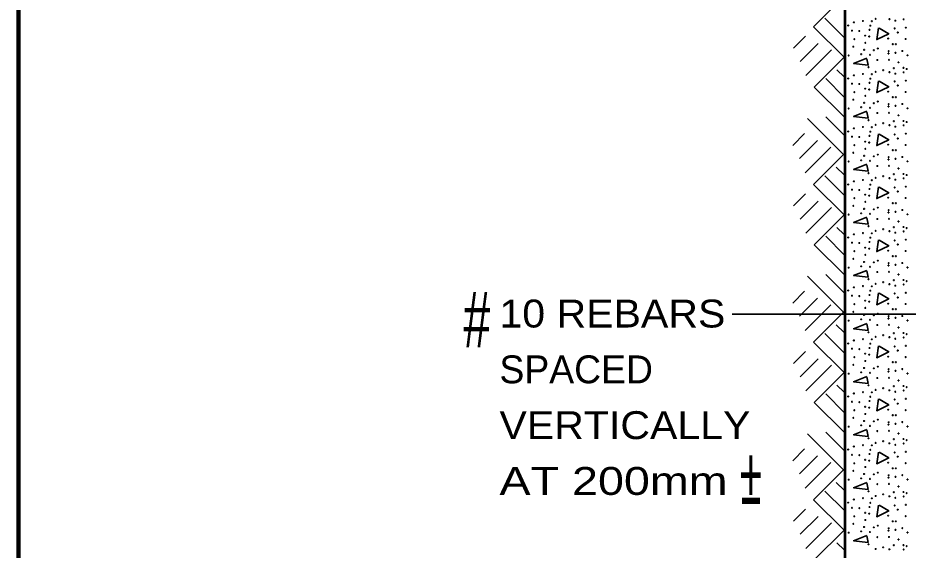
# Model space of a CAD drawing. Extents: x 442 to 1297, y -1132 to -588.
# Drawn here: x 499 to 575.6, y -964.6 to -918.8 of the extents above; entities that cross this region are included whole.
import ezdxf
from ezdxf.enums import TextEntityAlignment as Align

# ---------------------------------------------------------------- set-up
doc = ezdxf.new("R2010")
doc.units = 0
doc.header["$LTSCALE"] = 0.96
doc.layers.add('1', color=7, linetype='Continuous', lineweight=35)

msp = doc.modelspace()

# ---------------------------------------------------------------- linework, layer by layer
at = {"layer": '1', "lineweight": 53}
for q in [(570.1476, -980.7675), (570.1476, -980.5452)]:
    msp.add_line((570.1476, -886.6076), q, dxfattribs=at)
at = {"layer": '1'}
for p, q in [((570.0996, -916.8956), (567.4596, -919.5356)), ((570.0996, -920.4476), (568.4436, -918.7916)), ((570.0996, -922.1516), (567.4596, -919.5356)), ((566.7636, -920.3516), (565.7316, -921.3836)), ((567.8676, -920.9756), (566.3316, -922.5116)), ((569.0196, -921.5276), (566.8116, -923.7356)), ((570.0996, -922.1516), (567.5316, -924.7196)), ((570.0996, -923.8556), (569.4756, -923.2316)), ((570.0996, -925.5836), (568.5156, -923.9996)), ((570.0996, -927.2876), (567.5316, -924.7196)), ((570.0996, -930.5756), (566.9556, -927.4316)), ((570.0996, -928.8716), (568.5156, -927.2876)), ((566.6916, -928.7276), (565.6836, -929.7596)), ((567.7956, -929.3276), (566.2596, -930.8636)), ((568.9476, -929.8796), (566.7396, -932.1116)), ((570.0996, -930.4556), (567.4596, -933.0956)), ((570.0996, -932.2796), (569.4036, -931.6076)), ((570.0996, -934.0076), (568.4436, -932.3516)), ((570.0996, -935.7116), (567.4596, -933.0956)), ((566.7636, -933.9116), (565.7316, -934.9436)), ((567.8676, -934.5356), (566.3316, -936.0716)), ((569.0196, -935.0876), (566.8116, -937.2956)), ((570.0996, -935.7116), (567.5316, -938.2796)), ((570.0996, -937.4156), (569.4756, -936.7916)), ((570.0996, -939.1436), (568.5156, -937.5596)), ((570.0996, -940.8476), (567.5316, -938.2796)), ((570.0996, -942.4316), (568.5156, -940.8476)), ((570.0996, -944.1356), (566.9556, -940.9916)), ((566.6916, -942.2876), (565.6836, -943.3196)), ((567.7956, -942.8876), (566.2596, -944.4236)), ((568.9476, -943.4396), (566.7396, -945.6716)), ((560.4645, -944.2491), (579.7476, -944.2491)), ((570.0996, -944.0156), (567.4596, -946.6556)), ((570.0996, -945.8396), (569.4036, -945.1676)), ((570.0996, -947.5676), (568.4436, -945.9116)), ((570.0996, -949.2716), (567.4596, -946.6556)), ((566.7636, -947.4716), (565.7316, -948.5036)), ((567.8676, -948.0956), (566.3316, -949.6316)), ((569.0196, -948.6476), (566.8116, -950.8556)), ((570.0996, -949.2716), (567.5316, -951.8396)), ((570.0996, -950.9756), (569.4756, -950.3516)), ((570.0996, -952.7036), (568.5156, -951.1196)), ((570.0996, -954.4076), (567.5316, -951.8396)), ((570.0996, -957.6956), (566.9556, -954.5516)), ((570.0996, -955.9916), (568.5156, -954.4076)), ((566.6916, -955.8476), (565.6836, -956.8796)), ((567.7956, -956.4476), (566.2596, -957.9836)), ((568.9476, -956.9996), (566.7396, -959.2316)), ((570.0996, -957.5756), (567.4596, -960.2156)), ((570.0996, -959.3996), (569.4036, -958.7276)), ((570.0996, -961.1276), (568.4436, -959.4716)), ((570.0996, -962.8316), (567.4596, -960.2156)), ((566.7636, -961.0316), (565.7316, -962.0636)), ((567.8676, -961.6556), (566.3316, -963.1916)), ((569.0196, -962.2076), (566.8116, -964.4156)), ((570.0996, -962.8316), (567.5316, -965.3996)), ((570.0996, -964.5356), (569.4756, -963.9116))]:
    msp.add_line(p, q, dxfattribs=at)
at = {"layer": '1', "lineweight": 158}
msp.add_lwpolyline([(1290.7447, -594.0679), (499.0447, -594.1679), (499.1447, -1120.1679)], dxfattribs=at)
at = {"layer": '1'}
for points in [[(573.0974, -919.6547), (573.9374, -920.1347), (572.9054, -920.6387), (573.0494, -919.6307)], [(570.1476, -920.3222), (570.1694, -920.3267), (570.1476, -920.3501)], [(572.0414, -922.2467), (570.9134, -922.7027), (572.1614, -922.8467), (572.0414, -922.2947)], [(573.0974, -924.2147), (573.9374, -924.6947), (572.9054, -925.1987), (573.0494, -924.1907)], [(570.1476, -924.8822), (570.1694, -924.8867), (570.1476, -924.9101)], [(572.0414, -926.8067), (570.9134, -927.2627), (572.1614, -927.4067), (572.0414, -926.8547)], [(570.1476, -929.4422), (570.1694, -929.4467), (570.1476, -929.4701)], [(573.0974, -928.7747), (573.9374, -929.2547), (572.9054, -929.7587), (573.0494, -928.7507)], [(572.0414, -931.3667), (570.9134, -931.8227), (572.1614, -931.9667), (572.0414, -931.4147)], [(570.1476, -934.0022), (570.1694, -934.0067), (570.1476, -934.0301)], [(573.0974, -933.3347), (573.9374, -933.8147), (572.9054, -934.3187), (573.0494, -933.3107)], [(572.0414, -935.9267), (570.9134, -936.3827), (572.1614, -936.5267), (572.0414, -935.9747)], [(573.0974, -937.8947), (573.9374, -938.3747), (572.9054, -938.8787), (573.0494, -937.8707)], [(570.1476, -938.5622), (570.1694, -938.5667), (570.1476, -938.5901)], [(572.0414, -940.4867), (570.9134, -940.9427), (572.1614, -941.0867), (572.0414, -940.5347)], [(573.0974, -942.4547), (573.9374, -942.9347), (572.9054, -943.4387), (573.0494, -942.4307)], [(570.1476, -943.1222), (570.1694, -943.1267), (570.1476, -943.1501)], [(572.0414, -945.0467), (570.9134, -945.5027), (572.1614, -945.6467), (572.0414, -945.0947)], [(573.0974, -947.0147), (573.9374, -947.4947), (572.9054, -947.9987), (573.0494, -946.9907)], [(570.1476, -947.6822), (570.1694, -947.6867), (570.1476, -947.7101)], [(572.0414, -949.6067), (570.9134, -950.0627), (572.1614, -950.2067), (572.0414, -949.6547)], [(573.0974, -951.5747), (573.9374, -952.0547), (572.9054, -952.5587), (573.0494, -951.5507)], [(570.1476, -952.2422), (570.1694, -952.2467), (570.1476, -952.2701)], [(572.0414, -954.1667), (570.9134, -954.6227), (572.1614, -954.7667), (572.0414, -954.2147)], [(573.0974, -956.1347), (573.9374, -956.6147), (572.9054, -957.1187), (573.0494, -956.1107)], [(570.1476, -956.8022), (570.1694, -956.8067), (570.1476, -956.8301)], [(572.0414, -958.7267), (570.9134, -959.1827), (572.1614, -959.3267), (572.0414, -958.7747)], [(573.0974, -960.6947), (573.9374, -961.1747), (572.9054, -961.6787), (573.0494, -960.6707)], [(570.1476, -961.3622), (570.1694, -961.3667), (570.1476, -961.3901)], [(572.0414, -963.2867), (570.9134, -963.7427), (572.1614, -963.8867), (572.0414, -963.3347)]]:
    msp.add_lwpolyline(points, dxfattribs=at)
for centre in [(570.4458, -919.4227), (570.9388, -919.1523), (571.7181, -919.0409), (572.3542, -919.4386), (572.4814, -919.0568), (572.8154, -918.8501), (573.9923, -918.8818), (574.5013, -919.0091), (575.2168, -918.8977), (570.7797, -919.8682), (571.3999, -919.9), (571.9089, -920.2978), (572.2747, -919.8045), (574.4375, -919.6772), (574.708, -920.0273), (575.4077, -919.6136), (570.9705, -920.6), (571.9248, -920.9182), (572.2588, -920.3773), (573.8809, -920.5523), (574.2786, -921.0296), (574.5489, -921.0296), (575.3841, -920.5868), (570.8911, -921.2522), (571.8135, -921.5227), (572.6564, -921.5545), (572.9904, -921.4114), (573.9128, -921.8351), (573.9287, -921.6341), (574.5171, -921.7715), (575.1055, -921.6181), (570.4934, -922.0101), (571.559, -921.8987), (572.3224, -921.9465), (572.9585, -922.3919), (573.9605, -922.376), (574.7716, -922.5986), (575.5441, -921.9941), (572.1951, -923.0123), (573.4515, -923.2668), (574.3739, -923.0918), (575.201, -923.0759), (575.4805, -923.1714), (570.4458, -923.9827), (570.9388, -923.7123), (571.7181, -923.6009), (572.3542, -923.9986), (572.4814, -923.6168), (572.8154, -923.4101), (573.9923, -923.4418), (574.5013, -923.5691), (575.2168, -923.4577), (570.7797, -924.4282), (571.3999, -924.46), (571.9089, -924.8578), (572.2747, -924.3645), (574.4375, -924.2372), (574.708, -924.5873), (575.4077, -924.1736), (570.9705, -925.16), (571.9248, -925.4782), (572.2588, -924.9373), (573.8809, -925.1123), (574.2786, -925.5896), (574.5489, -925.5896), (575.3841, -925.1468), (570.8911, -925.8122), (571.8135, -926.0827), (572.6564, -926.1145), (572.9904, -925.9714), (573.9128, -926.3951), (573.9287, -926.1941), (574.5171, -926.3315), (575.1055, -926.1781), (570.4934, -926.5701), (571.559, -926.4587), (572.3224, -926.5065), (572.9585, -926.9519), (573.9605, -926.936), (574.7716, -927.1586), (575.5441, -926.5541), (572.1951, -927.5723), (573.4515, -927.8268), (574.3739, -927.6518), (575.201, -927.6359), (575.4805, -927.7314), (570.4458, -928.5427), (570.9388, -928.2723), (571.7181, -928.1609), (572.3542, -928.5586), (572.4814, -928.1768), (572.8154, -927.9701), (573.9923, -928.0018), (574.5013, -928.1291), (575.2168, -928.0177), (570.7797, -928.9882), (571.3999, -929.02), (571.9089, -929.4178), (572.2747, -928.9245), (574.4375, -928.7972), (574.708, -929.1473), (575.4077, -928.7336), (570.9705, -929.72), (571.9248, -930.0382), (572.2588, -929.4973), (573.8809, -929.6723), (574.2786, -930.1496), (574.5489, -930.1496), (575.3841, -929.7068), (570.8911, -930.3722), (571.559, -931.0187), (571.8135, -930.6427), (572.6564, -930.6745), (572.9904, -930.5314), (573.9128, -930.9551), (573.9287, -930.7541), (574.5171, -930.8915), (575.1055, -930.7381), (570.4934, -931.1301), (572.3224, -931.0665), (572.9585, -931.5119), (573.9605, -931.496), (574.7716, -931.7186), (575.5441, -931.1141), (572.1951, -932.1323), (572.8154, -932.5301), (573.4515, -932.3868), (574.3739, -932.2118), (575.201, -932.1959), (575.4805, -932.2914), (570.4458, -933.1027), (570.9388, -932.8323), (571.7181, -932.7209), (572.3542, -933.1186), (572.4814, -932.7368), (573.9923, -932.5618), (574.5013, -932.6891), (575.2168, -932.5777), (575.4077, -933.2936), (570.7797, -933.5482), (571.3999, -933.58), (571.9089, -933.9778), (572.2588, -934.0573), (572.2747, -933.4845), (574.4375, -933.3572), (574.708, -933.7073), (570.9705, -934.28), (571.9248, -934.5982), (573.8809, -934.2323), (574.2786, -934.7096), (574.5489, -934.7096), (575.3841, -934.2668), (570.8911, -934.9322), (571.559, -935.5787), (571.8135, -935.2027), (572.6564, -935.2345), (572.9904, -935.0914), (573.9128, -935.5151), (573.9287, -935.3141), (574.5171, -935.4515), (575.1055, -935.2981), (570.4934, -935.6901), (572.3224, -935.6265), (572.9585, -936.0719), (573.9605, -936.056), (574.7716, -936.2786), (575.5441, -935.6741), (572.1951, -936.6923), (572.8154, -937.0901), (573.4515, -936.9468), (573.9923, -937.1218), (574.3739, -936.7718), (575.201, -936.7559), (575.2168, -937.1377), (575.4805, -936.8514), (570.4458, -937.6627), (570.9388, -937.3923), (571.7181, -937.2809), (572.3542, -937.6786), (572.4814, -937.2968), (574.5013, -937.2491), (575.4077, -937.8536), (570.7797, -938.1082), (571.3999, -938.14), (571.9089, -938.5378), (572.2588, -938.6173), (572.2747, -938.0445), (574.4375, -937.9172), (574.708, -938.2673), (570.9705, -938.84), (571.9248, -939.1582), (573.8809, -938.7923), (574.2786, -939.2696), (574.5489, -939.2696), (575.3841, -938.8268), (570.8911, -939.4922), (571.559, -940.1387), (571.8135, -939.7627), (572.3224, -940.1865), (572.6564, -939.7945), (572.9904, -939.6514), (573.9128, -940.0751), (573.9287, -939.8741), (574.5171, -940.0115), (575.1055, -939.8581), (570.4934, -940.2501), (572.9585, -940.6319), (573.9605, -940.616), (574.7716, -940.8386), (575.5441, -940.2341), (572.1951, -941.2523), (572.8154, -941.6501), (573.4515, -941.5068), (573.9923, -941.6818), (574.3739, -941.3318), (575.201, -941.3159), (575.2168, -941.6977), (575.4805, -941.4114), (570.4458, -942.2227), (570.9388, -941.9523), (571.7181, -941.8409), (572.3542, -942.2386), (572.4814, -941.8568), (574.4375, -942.4772), (574.5013, -941.8091), (575.4077, -942.4136), (570.7797, -942.6682), (571.3999, -942.7), (571.9089, -943.0978), (572.2588, -943.1773), (572.2747, -942.6045), (574.708, -942.8273), (570.9705, -943.4), (571.9248, -943.7182), (573.8809, -943.3523), (574.2786, -943.8296), (574.5489, -943.8296), (575.3841, -943.3868), (570.8911, -944.0522), (571.559, -944.6987), (571.8135, -944.3227), (572.3224, -944.7465), (572.6564, -944.3545), (572.9904, -944.2114), (573.9128, -944.6351), (573.9287, -944.4341), (574.5171, -944.5715), (575.1055, -944.4181), (575.5441, -944.7941), (570.4934, -944.8101), (572.9585, -945.1919), (573.9605, -945.176), (574.7716, -945.3986), (572.1951, -945.8123), (572.8154, -946.2101), (573.4515, -946.0668), (573.9923, -946.2418), (574.3739, -945.8918), (575.201, -945.8759), (575.2168, -946.2577), (575.4805, -945.9714), (570.4458, -946.7827), (570.9388, -946.5123), (571.7181, -946.4009), (572.3542, -946.7986), (572.4814, -946.4168), (574.4375, -947.0372), (574.5013, -946.3691), (575.4077, -946.9736), (570.7797, -947.2282), (571.3999, -947.26), (571.9089, -947.6578), (572.2588, -947.7373), (572.2747, -947.1645), (574.708, -947.3873), (570.8911, -948.6122), (570.9705, -947.96), (571.9248, -948.2782), (573.8809, -947.9123), (574.2786, -948.3896), (574.5489, -948.3896), (575.3841, -947.9468), (570.4934, -949.3701), (571.559, -949.2587), (571.8135, -948.8827), (572.3224, -949.3065), (572.6564, -948.9145), (572.9904, -948.7714), (573.9128, -949.1951), (573.9287, -948.9941), (574.5171, -949.1315), (575.1055, -948.9781), (575.5441, -949.3541), (572.9585, -949.7519), (573.9605, -949.736), (574.7716, -949.9586), (572.1951, -950.3723), (572.8154, -950.7701), (573.4515, -950.6268), (573.9923, -950.8018), (574.3739, -950.4518), (574.5013, -950.9291), (575.201, -950.4359), (575.2168, -950.8177), (575.4805, -950.5314), (570.4458, -951.3427), (570.9388, -951.0723), (571.7181, -950.9609), (572.3542, -951.3586), (572.4814, -950.9768), (574.4375, -951.5972), (575.4077, -951.5336), (570.7797, -951.7882), (571.3999, -951.82), (571.9089, -952.2178), (572.2588, -952.2973), (572.2747, -951.7245), (574.708, -951.9473), (570.8911, -953.1722), (570.9705, -952.52), (571.9248, -952.8382), (573.8809, -952.4723), (574.2786, -952.9496), (574.5489, -952.9496), (575.3841, -952.5068), (570.4934, -953.9301), (571.559, -953.8187), (571.8135, -953.4427), (572.3224, -953.8665), (572.6564, -953.4745), (572.9904, -953.3314), (573.9128, -953.7551), (573.9287, -953.5541), (574.5171, -953.6915), (575.1055, -953.5381), (575.5441, -953.9141), (572.9585, -954.3119), (573.9605, -954.296), (574.7716, -954.5186), (571.7181, -955.5209), (572.1951, -954.9323), (572.8154, -955.3301), (573.4515, -955.1868), (573.9923, -955.3618), (574.3739, -955.0118), (574.5013, -955.4891), (575.201, -954.9959), (575.2168, -955.3777), (575.4805, -955.0914), (570.4458, -955.9027), (570.9388, -955.6323), (572.2747, -956.2845), (572.3542, -955.9186), (572.4814, -955.5368), (574.4375, -956.1572), (575.4077, -956.0936), (570.7797, -956.3482), (571.3999, -956.38), (571.9089, -956.7778), (572.2588, -956.8573), (573.8809, -957.0323), (574.708, -956.5073), (570.8911, -957.7322), (570.9705, -957.08), (571.9248, -957.3982), (574.2786, -957.5096), (574.5489, -957.5096), (575.3841, -957.0668), (570.4934, -958.4901), (571.559, -958.3787), (571.8135, -958.0027), (572.3224, -958.4265), (572.6564, -958.0345), (572.9904, -957.8914), (573.9128, -958.3151), (573.9287, -958.1141), (574.5171, -958.2515), (575.1055, -958.0981), (575.5441, -958.4741), (572.9585, -958.8719), (573.9605, -958.856), (574.7716, -959.0786), (571.7181, -960.0809), (572.1951, -959.4923), (572.4814, -960.0968), (572.8154, -959.8901), (573.4515, -959.7468), (573.9923, -959.9218), (574.3739, -959.5718), (574.5013, -960.0491), (575.201, -959.5559), (575.2168, -959.9377), (575.4805, -959.6514), (570.4458, -960.4627), (570.9388, -960.1923), (572.2747, -960.8445), (572.3542, -960.4786), (574.4375, -960.7172), (575.4077, -960.6536), (570.7797, -960.9082), (570.9705, -961.64), (571.3999, -960.94), (571.9089, -961.3378), (572.2588, -961.4173), (573.8809, -961.5923), (574.708, -961.0673), (575.3841, -961.6268), (570.8911, -962.2922), (571.9248, -961.9582), (574.2786, -962.0696), (574.5489, -962.0696), (570.4934, -963.0501), (571.559, -962.9387), (571.8135, -962.5627), (572.3224, -962.9865), (572.6564, -962.5945), (572.9904, -962.4514), (573.9128, -962.8751), (573.9287, -962.6741), (574.5171, -962.8115), (575.1055, -962.6581), (575.5441, -963.0341), (572.9585, -963.4319), (573.9605, -963.416), (574.7716, -963.6386), (572.1951, -964.0523), (572.8154, -964.4501), (573.4515, -964.3068), (573.9923, -964.4818), (574.3739, -964.1318), (575.201, -964.1159), (575.2168, -964.4977), (575.4805, -964.2114)]:
    msp.add_circle(centre, 0.0318, dxfattribs=at)

# ---------------------------------------------------------------- texts
for s, width, p in [('#', 0.65, (538.5189, -947.1173)), ('+', 0.55, (562.0768, -960.4312))]:
    msp.add_text(s, height=4.8, dxfattribs=dict(at, width=width)).set_placement(p, align=Align.CENTER)
for s, width, p in [('10 REBARS', 1.1, (540.4603, -945.4024)), ('VERTICALLY', 1.1, (540.4603, -955.0024)), ('AT 200mm', 1.25, (540.4603, -959.8024))]:
    msp.add_text(s, height=2.4, dxfattribs=dict(at, width=width)).set_placement(p)
msp.add_text('SPACED', height=2.4, dxfattribs=at).set_placement((540.4603, -950.2024))
msp.add_text('-', height=4.8, dxfattribs=at).set_placement((562.0873, -962.1516), align=Align.CENTER)

doc.saveas('drawing.dxf')
